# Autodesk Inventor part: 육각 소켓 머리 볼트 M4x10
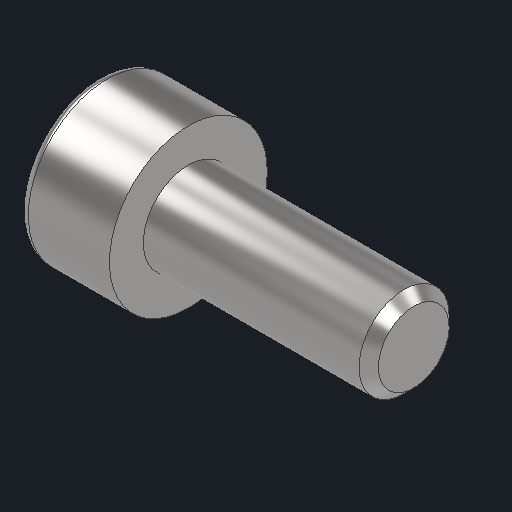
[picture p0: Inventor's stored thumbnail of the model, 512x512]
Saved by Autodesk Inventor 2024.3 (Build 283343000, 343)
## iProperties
Created: 2024-05
Part Number: 육각 소켓 머리 볼트 M4x10
Material: 강철, 연강
Description: 6각머리 태핑 나사
Document SubType Name: Modeling
Designer: MyPc
Density: 7.85 g/cm^3
Appearance: 기본값
Author: jhkim
Sending System: Autodesk Inventor 2025
Preprocessor: ST-DEVELOPER v20
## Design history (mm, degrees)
node "육각 소켓 머리 볼트 M4x101"
node "솔리드1"
body "Solid1"
